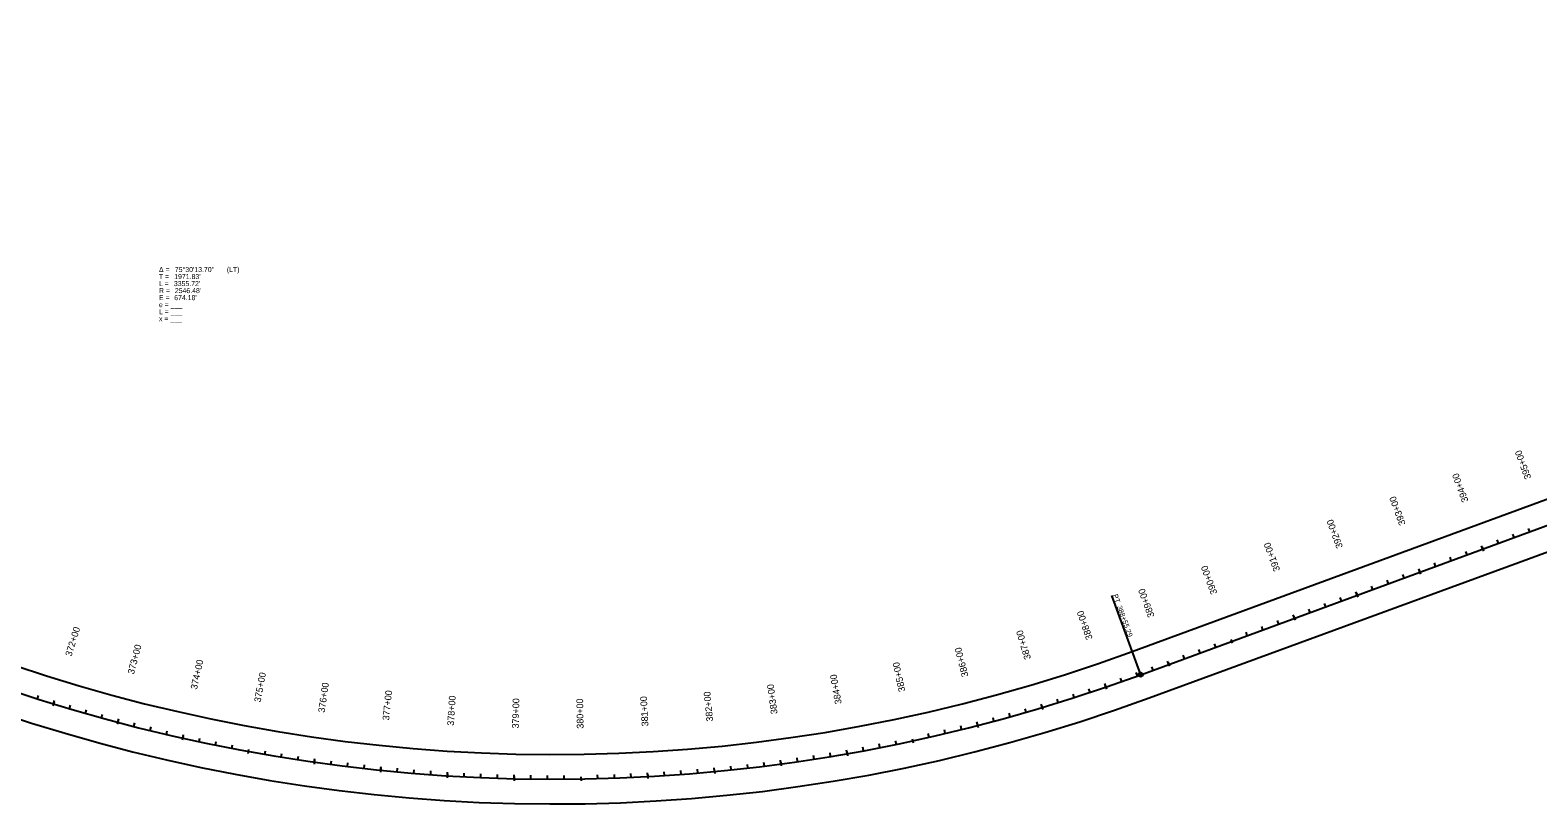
# Model space of a CAD drawing. Extents: x 21369364 to 21378321, y 8396964 to 8399934.
# Drawn here: x 21371598 to 21373853, y 8397576 to 8398732 of the extents above; entities that cross this region are included whole.
import ezdxf

# ---------------------------------------------------------------- set-up
doc = ezdxf.new("R2010")
doc.units = 0
for name, color, linetype in [('Alignment', 7, 'Continuous'), ('Level 1', 7, 'Continuous'), ('Level 60', 7, 'Continuous'), ('TextNonPlot', 7, 'Continuous')]:
    doc.layers.add(name, color=color, linetype=linetype)

msp = doc.modelspace()

# ---------------------------------------------------------------- linework, layer by layer
at = {"layer": 'Alignment'}
msp.add_line((21373258.8, 8397768.9), (21374821.1, 8398342.5), dxfattribs=at)
msp.add_arc((21372381.2, 8400159.4), 2546.5, 214.6562, 290.16, dxfattribs=at)
at = {"layer": 'Level 1'}
for p in [(21373258.8, 8397768.9), (21373215.4, 8397887.2)]:
    msp.add_line(p, (21373215.4, 8397887.2), dxfattribs=at)
msp.add_circle((21373258.8, 8397768.9), 3.12, dxfattribs=at)
at = {"layer": 'Level 60'}
for p, q in [((21373793.6, 8397965.3), (21373791.7, 8397970.4)), ((21373817.1, 8397973.9), (21373815.2, 8397979)), ((21373840.6, 8397982.5), (21373838.7, 8397987.6)), ((21373723.2, 8397939.4), (21373721.3, 8397944.5)), ((21373746.7, 8397948), (21373744.8, 8397953.2)), ((21373769.1, 8397959.5), (21373771.2, 8397953.8)), ((21373675.2, 8397925.1), (21373677.3, 8397919.3)), ((21373699.7, 8397930.8), (21373697.9, 8397935.9)), ((21373605.9, 8397896.3), (21373604, 8397901.5)), ((21373629.3, 8397904.9), (21373627.5, 8397910.1)), ((21373652.8, 8397913.6), (21373650.9, 8397918.7)), ((21373558.9, 8397879.1), (21373557.1, 8397884.2)), ((21373581.3, 8397890.6), (21373583.5, 8397884.8)), ((21373487.5, 8397856.1), (21373489.6, 8397850.4)), ((21373512, 8397861.9), (21373510.1, 8397867)), ((21373535.5, 8397870.5), (21373533.6, 8397875.6)), ((21373418.1, 8397827.4), (21373416.2, 8397832.5)), ((21373441.6, 8397836), (21373439.7, 8397841.1)), ((21373465.1, 8397844.6), (21373463.2, 8397849.8)), ((21373371.2, 8397810.2), (21373369.3, 8397815.3)), ((21373393.6, 8397821.7), (21373395.7, 8397815.9)), ((21373299.7, 8397787.2), (21373301.8, 8397781.5)), ((21373324.2, 8397792.9), (21373322.4, 8397798.1)), ((21373347.7, 8397801.6), (21373345.8, 8397806.7)), ((21373253.8, 8397767.1), (21373252, 8397772.2)), ((21373277.3, 8397775.7), (21373275.4, 8397780.8)), ((21373183, 8397742.4), (21373181.3, 8397747.6)), ((21373205.7, 8397753.3), (21373207.7, 8397747.5)), ((21373230.3, 8397758.6), (21373228.5, 8397763.8)), ((21371609.2, 8397732.7), (21371610.9, 8397737.9)), ((21371634, 8397728.2), (21371632.2, 8397722.3)), ((21371657, 8397718), (21371658.6, 8397723.3)), ((21373110.6, 8397722.8), (21373112.4, 8397716.9)), ((21373135.4, 8397727.2), (21373133.8, 8397732.4)), ((21373159.2, 8397734.7), (21373157.6, 8397739.9)), ((21371681, 8397711), (21371682.5, 8397716.3)), ((21371705.1, 8397704.3), (21371706.5, 8397709.6)), ((21371730, 8397700.7), (21371728.5, 8397694.8)), ((21371753.4, 8397691.5), (21371754.8, 8397696.8)), ((21373039.3, 8397699.4), (21373037.9, 8397704.7)), ((21373063.5, 8397706), (21373062, 8397711.3)), ((21373087.5, 8397712.8), (21373086, 8397718.1)), ((21371777.7, 8397685.4), (21371779, 8397690.8)), ((21371802, 8397679.6), (21371803.2, 8397685)), ((21371827, 8397677.1), (21371825.7, 8397671.1)), ((21371850.8, 8397668.7), (21371851.9, 8397674.1)), ((21372942.3, 8397675.5), (21372941, 8397680.8)), ((21372966.6, 8397681.1), (21372965.4, 8397686.4)), ((21372990.9, 8397687), (21372989.6, 8397692.3)), ((21373014.4, 8397696), (21373015.9, 8397690.1)), ((21371875.3, 8397663.7), (21371876.4, 8397669)), ((21371899.8, 8397658.8), (21371900.8, 8397664.2)), ((21371924.9, 8397657.2), (21371923.8, 8397651.2)), ((21371949, 8397649.8), (21371949.9, 8397655.2)), ((21372795, 8397646.8), (21372794.2, 8397652.1)), ((21372819.2, 8397654), (21372820.2, 8397647.9)), ((21372844.3, 8397655.4), (21372843.3, 8397660.7)), ((21372868.9, 8397660), (21372867.8, 8397665.4)), ((21372893.4, 8397664.9), (21372892.3, 8397670.3)), ((21372917.2, 8397673.1), (21372918.5, 8397667.1)), ((21371973.7, 8397645.7), (21371974.5, 8397651.1)), ((21371998.4, 8397641.8), (21371999.2, 8397647.2)), ((21372023.5, 8397641.2), (21372022.7, 8397635.2)), ((21372047.9, 8397634.8), (21372048.6, 8397640.2)), ((21372072.7, 8397631.7), (21372073.3, 8397637.1)), ((21372097.5, 8397628.8), (21372098.1, 8397634.2)), ((21372122.7, 8397629.1), (21372122, 8397623)), ((21372147.2, 8397623.7), (21372147.7, 8397629.1)), ((21372646.4, 8397626.8), (21372645.8, 8397632.2)), ((21372671.3, 8397629.5), (21372670.6, 8397634.9)), ((21372696.1, 8397632.4), (21372695.4, 8397637.9)), ((21372720.5, 8397638.7), (21372721.3, 8397632.6)), ((21372745.6, 8397639.1), (21372744.9, 8397644.5)), ((21372770.4, 8397642.8), (21372769.5, 8397648.2)), ((21372172.1, 8397621.5), (21372172.6, 8397626.9)), ((21372197.1, 8397619.6), (21372197.4, 8397625)), ((21372222.2, 8397620.9), (21372221.8, 8397614.8)), ((21372247, 8397616.4), (21372247.2, 8397621.9)), ((21372271.9, 8397615.2), (21372272.2, 8397620.7)), ((21372296.9, 8397614.3), (21372297.1, 8397619.8)), ((21372322, 8397616.7), (21372321.8, 8397610.5)), ((21372346.9, 8397613.1), (21372347, 8397618.6)), ((21372371.9, 8397612.9), (21372371.9, 8397618.4)), ((21372396.9, 8397613), (21372396.9, 8397618.4)), ((21372421.8, 8397616.3), (21372421.9, 8397610.2)), ((21372446.9, 8397613.7), (21372446.7, 8397619.2)), ((21372471.9, 8397614.5), (21372471.7, 8397620)), ((21372496.9, 8397615.5), (21372496.6, 8397621)), ((21372521.7, 8397619.8), (21372522, 8397613.7)), ((21372546.8, 8397618.3), (21372546.4, 8397623.7)), ((21372571.7, 8397620), (21372571.3, 8397625.5)), ((21372596.6, 8397622), (21372596.2, 8397627.5)), ((21372621.2, 8397627.3), (21372621.8, 8397621.2))]:
    msp.add_line(p, q, dxfattribs=at)
at = {"layer": 'TextNonPlot'}
for p, q in [((21373246.1, 8397803.6), (21374808.3, 8398377.2)), ((21373271.6, 8397734.2), (21374833.8, 8398307.8)), ((21373770.1, 8397956.6), (21373768.3, 8397961.8)), ((21373676.3, 8397922.2), (21373674.4, 8397927.3)), ((21373582.4, 8397887.7), (21373580.5, 8397892.8)), ((21373488.5, 8397853.3), (21373486.6, 8397858.4)), ((21373393.6, 8397821.7), (21373395.7, 8397815.9)), ((21373300.8, 8397784.3), (21373298.9, 8397789.4)), ((21373206.7, 8397750.4), (21373204.9, 8397755.6)), ((21371633.1, 8397725.3), (21371634.7, 8397730.5)), ((21373111.5, 8397719.9), (21373109.9, 8397725.1)), ((21371729.2, 8397697.8), (21371730.6, 8397703.1)), ((21373015.2, 8397693.1), (21373013.8, 8397698.4)), ((21371826.4, 8397674.1), (21371827.6, 8397679.4)), ((21371924.9, 8397657.2), (21371923.8, 8397651.2)), ((21372819.7, 8397650.9), (21372818.8, 8397656.3)), ((21372917.2, 8397673.1), (21372918.5, 8397667.1)), ((21372023.1, 8397638.2), (21372023.9, 8397643.6)), ((21372122.3, 8397626.1), (21372122.9, 8397631.5)), ((21372621.5, 8397624.3), (21372621, 8397629.7)), ((21372720.9, 8397635.7), (21372720.1, 8397641.1)), ((21372222, 8397617.9), (21372222.3, 8397623.3)), ((21372321.9, 8397613.6), (21372322, 8397619.1)), ((21372421.8, 8397616.3), (21372421.9, 8397610.2)), ((21372521.8, 8397616.8), (21372521.5, 8397622.2))]:
    msp.add_line(p, q, dxfattribs=at)
for radius in [2509.5, 2583.5]:
    msp.add_arc((21372381.2, 8400159.4), radius, 214.6562, 290.16, dxfattribs=at)

# ---------------------------------------------------------------- texts
at = {"layer": 'Level 1'}
for s, p in [('Δ = ', (21371790.8, 8398370.8)), ('75°30\'13.70"', (21371814.5, 8398370.8)), (' (LT)', (21371889.4, 8398370.8)), ('T = ', (21371790.8, 8398360.3)), ('L = ', (21371790.8, 8398349.8)), ("3355.72'", (21371813.1, 8398349.8)), ("1971.83'", (21371813.6, 8398360.3)), ('R = ', (21371790.8, 8398339.3)), ('E = ', (21371790.8, 8398328.8)), ("674.18'", (21371813.6, 8398328.8)), ("2546.48'", (21371814.5, 8398339.3)), ('e = ___ ', (21371790.8, 8398318.3)), ('L = ___', (21371790.8, 8398307.8)), ('x = ___', (21371790.8, 8398297.3))]:
    msp.add_text(s, height=7.5, dxfattribs=at).set_placement(p)
for s, p in [('PT', (21373216.9, 8397887.8)), ('388+55.29', (21373223.2, 8397870.7))]:
    msp.add_text(s, height=7.5, rotation=290.16, dxfattribs=at).set_placement(p)
at = {"layer": 'Level 60'}
for s, rotation, p in [('395+00', 110.16, (21373842.9, 8398063.2)), ('394+00', 110.16, (21373749, 8398028.8)), ('393+00', 110.16, (21373655.1, 8397994.3)), ('392+00', 110.16, (21373561.3, 8397959.8)), ('391+00', 110.16, (21373467.4, 8397925.4)), ('390+00', 110.16, (21373373.5, 8397890.9)), ('389+00', 110.16, (21373279.6, 8397856.5)), ('388+00', 108.916, (21373187.1, 8397823)), ('372+00', 72.916, (21371659.9, 8397795.5)), ('387+00', 106.666, (21373094.8, 8397793.2)), ('373+00', 75.166, (21371753.3, 8397769)), ('386+00', 104.416, (21373001.3, 8397767)), ('374+00', 77.416, (21371847.6, 8397746.2)), ('385+00', 102.166, (21372906.9, 8397744.5)), ('375+00', 79.666, (21371942.8, 8397727.1)), ('384+00', 99.916, (21372811.7, 8397725.7)), ('376+00', 81.916, (21372038.6, 8397711.8)), ('377+00', 84.166, (21372134.9, 8397700.2)), ('382+00', 95.416, (21372619.4, 8397699.4)), ('383+00', 97.666, (21372715.8, 8397710.7)), ('378+00', 86.416, (21372231.7, 8397692.4)), ('379+00', 88.666, (21372328.7, 8397688.5)), ('380+00', 90.916, (21372425.7, 8397688.3)), ('381+00', 93.166, (21372522.7, 8397692))]:
    msp.add_text(s, height=10.02, rotation=rotation, dxfattribs=at).set_placement(p)
at = {"layer": 'TextNonPlot'}
for s, rotation, p in [('395+00', 110.16, (21373842.9, 8398063.2)), ('390+00', 110.16, (21373373.5, 8397890.9)), ('385+00', 102.166, (21372906.9, 8397744.5)), ('375+00', 79.666, (21371942.8, 8397727.1)), ('380+00', 90.916, (21372425.7, 8397688.3))]:
    msp.add_text(s, height=10.02, rotation=rotation, dxfattribs=at).set_placement(p)

doc.saveas('drawing.dxf')
